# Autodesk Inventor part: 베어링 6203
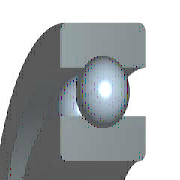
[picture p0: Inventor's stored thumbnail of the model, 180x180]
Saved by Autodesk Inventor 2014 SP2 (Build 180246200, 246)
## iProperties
IsCustomPart: 0
Company: 한국ATC센터
Created: 2014-10
Part Number: 베어링 6203
Material: Steel, Mild
Description: 깊은 그루브 볼 베어링
Document SubType Name: Modeling
Standard: KS B 2023
Designer: KYOUNG IL JANG
Standards Organization: KS
Language: ko-KR
Size Designation: 6203 - 17 x 40 x 12
Categories: <MemberInstance><Categories><Category DisplayName="샤프트 부품" InternalName="7f7aeb1f-a693-4053-b835-cee3144e0d98" Mnemonic="SHFT"><Category DisplayName="베어링" Inter
Density: 7.86 g/cm^3
Mass: 64.9809 g
Surface Area: 64.3582 cm^2
Volume: 8.26729 cm^3
Appearance: 강철 - 광택
Author: KYOUNG IL JANG
Revision Number: 1
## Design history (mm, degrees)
sketch "스케치" dims "d0" = 5.98 (= -0.26 x WD + 0.26 x BD)
  geometry: L1 (3.01, 14.25)-(8.99, 14.25); L2 (6, 14.25)-(6, 11.26); L3 (6, 14.25)-(6, 17.24); L4 (3.778, 12.249)-(0, 12.249); L5 (0, 8.5)-(12, 8.5); L6 (3.778, 16.251)-(0, 16.251); L7 (0, 20)-(12, 20); L8 (12, 8.5)-(12, 12.249); L9 (8.222, 12.249)-(12, 12.249); L10 (8.222, 16.251)-(12, 16.251); L11 (12, 20)-(12, 16.251); L12 (-1.4, 0)-(8.4, 0) reference; L13 (0, -0.3)-(0, 5.3) reference
  constraints: 22 end point, 4 point on line, 2 collinear, 2 perpendicular, 2 symmetric about line, 1 midpoint, 1 parallel, 14 other
  dimensions: "d9" = 17 diameter of L5 L12 (= WD); "d11" = 40 diameter of L7 L12 (= BD); "d12" = 12 distance between parallel lines of L8 L13 (= KB); "d13" = 24.498 diameter of L9 L12 (= 0.326 x BD + 0.674 x WD)
revolve "본체" stored, may be unused: angle "d6" = 90 deg
revolve "볼" stored, may be unused: angle "d7" = 90 deg
pattern_circular "IDS_ARRAYBALL[SIMPL:T]" dims angle "d3" = 360 deg
body "Solid1"
fillet "모깎기1" dims "d1" = 0.6 (= KRS)
other parameters: "WD" = 17 [user parameter; used in 5 equation terms], "BD" = 40 [user parameter; used in 5 equation terms], "KB" = 12 [user parameter; used in 1 equation term], "KRS" = 0.6 [user parameter; used in 1 equation term], "d4" = 0, "d5" = 0, "d8" = 0, "d14" = 0, "d15" = 0, "BBA" = 0 [user parameter], "BC0" = 4750000 [user parameter], "BC" = 9560000 [user parameter], "WR" = 8.5 (= 0.5 x WD) [user parameter]
